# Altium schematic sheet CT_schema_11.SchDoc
size 387 x 278 mm
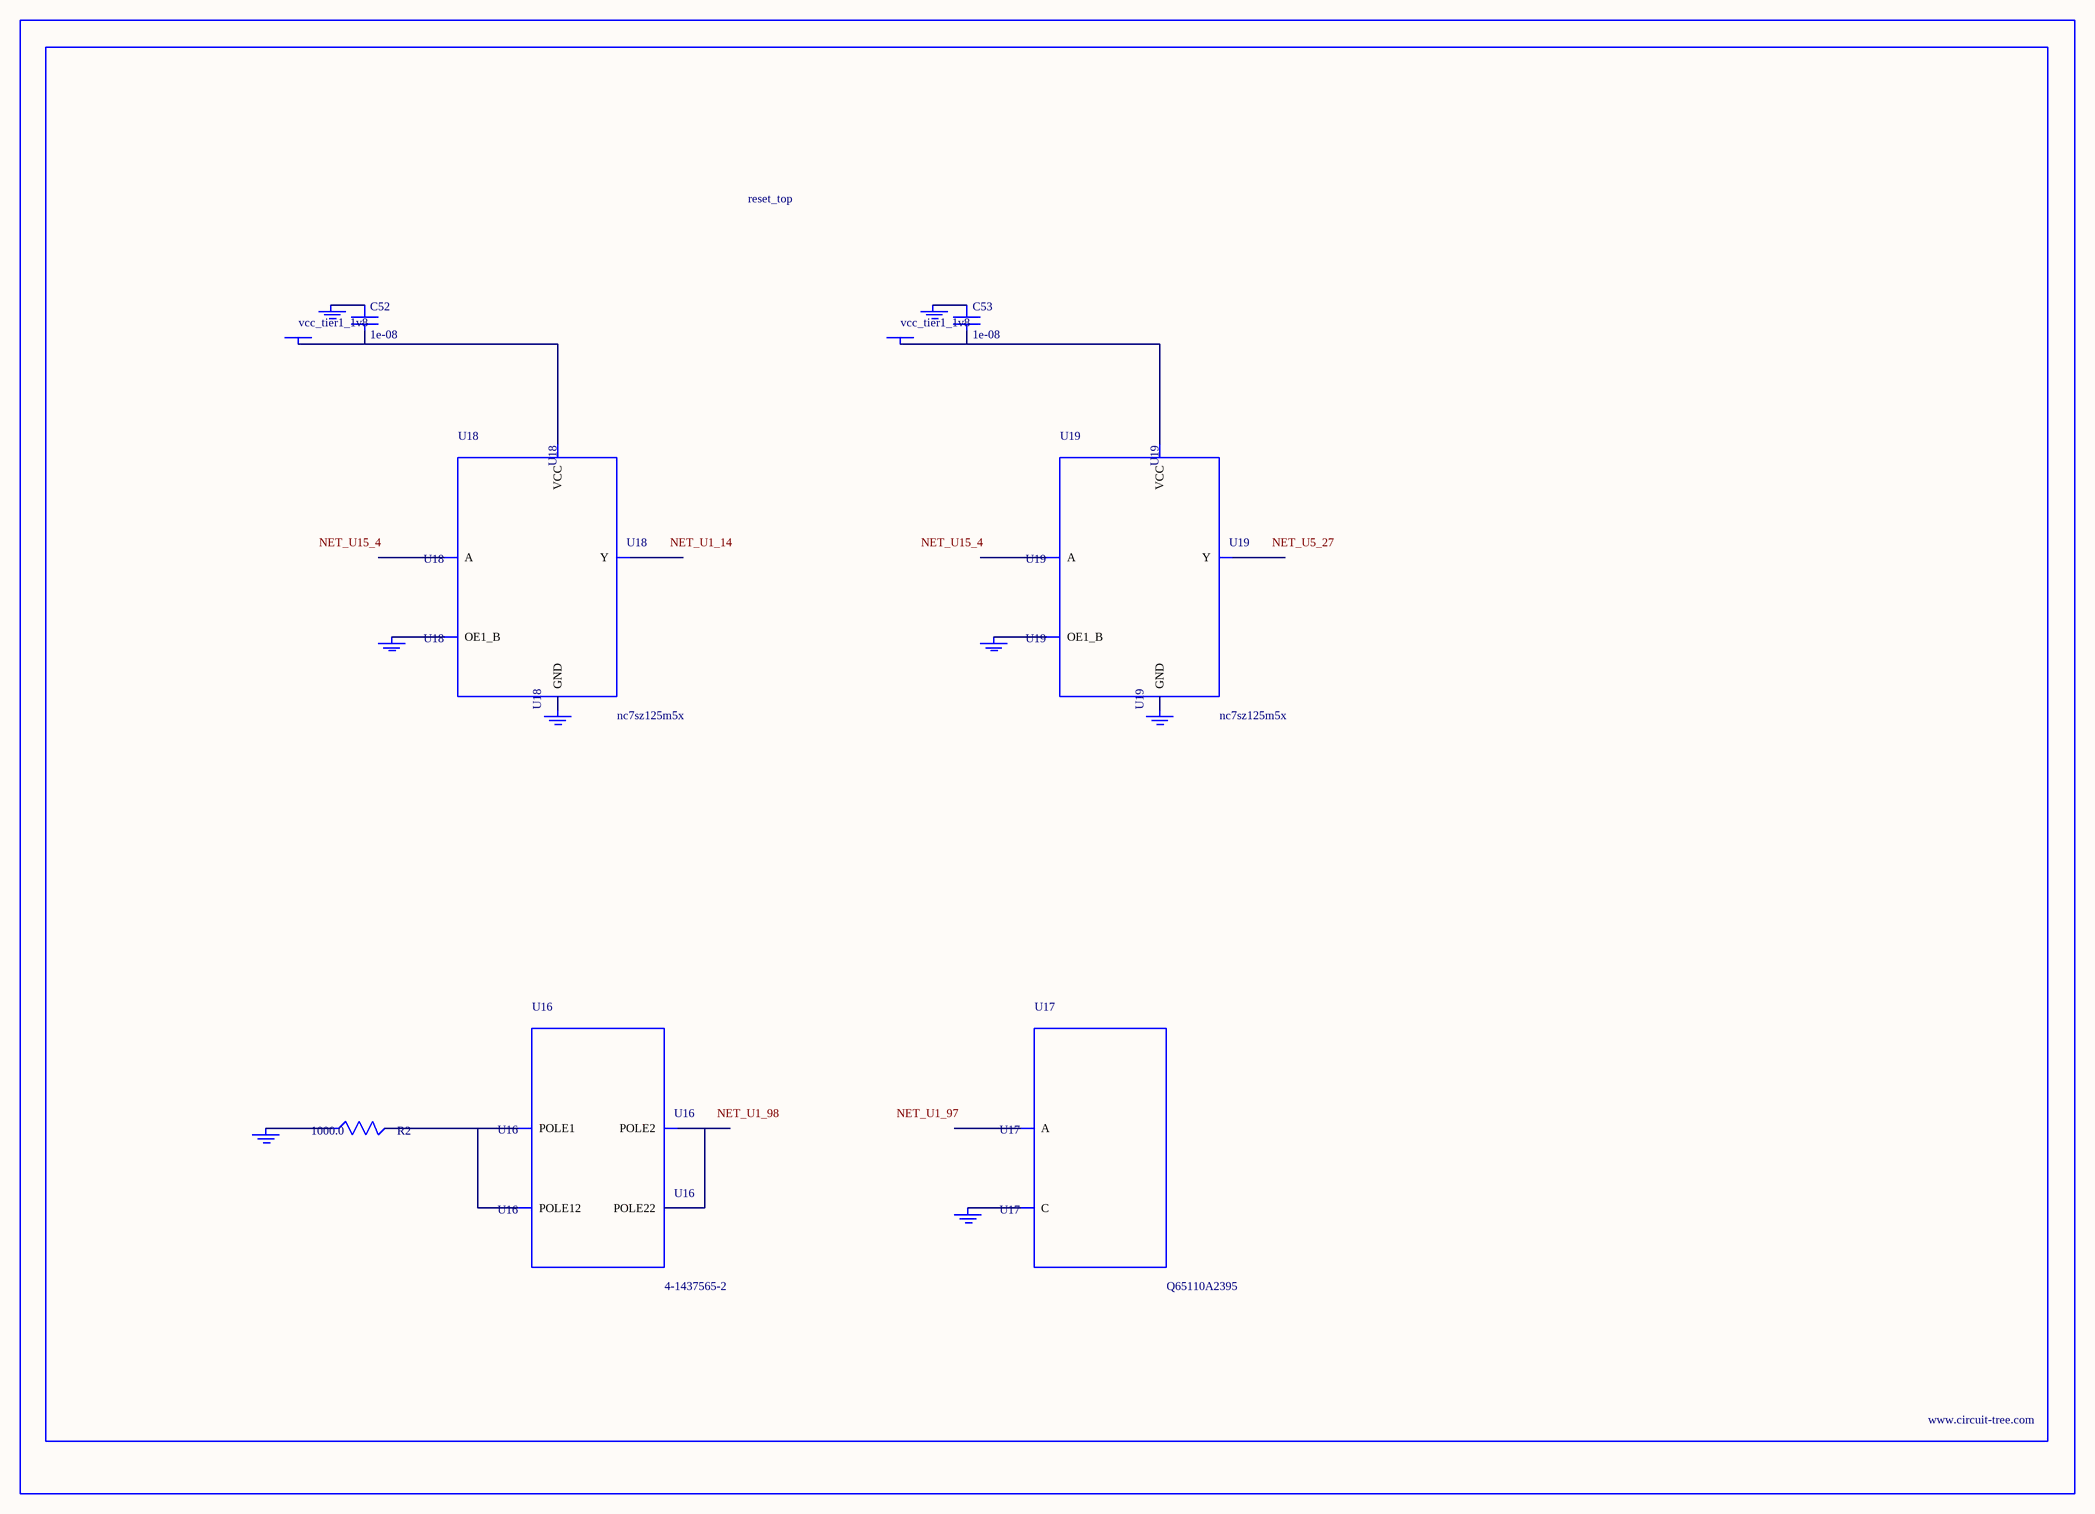
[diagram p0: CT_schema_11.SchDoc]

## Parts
BORDER10  (no value)
C52  1e-08  [C0402]
C53  1e-08  [C0402]
GND_INSTANCE_10_0  (no value)
GND_INSTANCE_10_1  (no value)
GND_INSTANCE_10_2  (no value)
GND_INSTANCE_10_3  (no value)
GND_INSTANCE_10_4  (no value)
GND_INSTANCE_10_5  (no value)
GND_INSTANCE_10_6  (no value)
GND_INSTANCE_10_7  (no value)
POWER_INSTANCE_10_0  vcc_tier1_1v8
POWER_INSTANCE_10_1  vcc_tier1_1v8
R2  1000.0  [R0603]
U16  4-1437565-2  [SW_4-1437565-2]
U17  Q65110A2395  [LGM67K-G1J2-24-Z]
U18  nc7sz125m5x  [NC7SZ125M5X]
U19  nc7sz125m5x  [NC7SZ125M5X]

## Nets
NetC52_1: C52.1 GND_INSTANCE_10_2.0(GND)
NetC52_2: C52.2 POWER_INSTANCE_10_0.0(PWR) U18.5(VCC)
NetC53_1: C53.1 GND_INSTANCE_10_5.0(GND)
NetC53_2: C53.2 POWER_INSTANCE_10_1.0(PWR) U19.5(VCC)
NetGND_INSTANCE_10_0_0: GND_INSTANCE_10_0.0(GND) R2.1
NetGND_INSTANCE_10_1_0: GND_INSTANCE_10_1.0(GND) U17.C
NetGND_INSTANCE_10_3_0: GND_INSTANCE_10_3.0(GND) U18.1(OE1_B)
NetGND_INSTANCE_10_4_0: GND_INSTANCE_10_4.0(GND) U18.3(GND)
NetGND_INSTANCE_10_6_0: GND_INSTANCE_10_6.0(GND) U19.1(OE1_B)
NetGND_INSTANCE_10_7_0: GND_INSTANCE_10_7.0(GND) U19.3(GND)
NetR2_2: R2.2 U16.1(POLE1) U16.2(POLE12)
NetU16_3: U16.3(POLE2) U16.4(POLE22)

Not connected (* = marked no-connect by the designer): U17 A; U18 2(A) 4(Y); U19 2(A) 4(Y)

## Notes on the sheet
- Labels drawn without touching a wire or pin: NET_U1_14, NET_U1_97, NET_U1_98, NET_U5_27, NET_U15_4

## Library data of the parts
BORDER10 = BORDER_PAGE10
C52 C53 = C0402C103K3RAC
GND_INSTANCE_10_0-GND_INSTANCE_10_7 = GND
POWER_INSTANCE_10_0 POWER_INSTANCE_10_1 = PWR
R2 = RC0603JR-071KL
